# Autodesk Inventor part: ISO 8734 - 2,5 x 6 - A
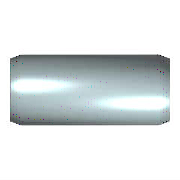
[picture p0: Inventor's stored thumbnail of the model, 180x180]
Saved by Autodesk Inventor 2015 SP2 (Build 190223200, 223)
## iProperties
IsCustomPart: 0
Created: 2012-02
Part Number: ISO 8734 - 2,5 x 6 - A
Material: Stahl
Description: Zylinderstift
Document SubType Name: Modeling
Standard: ISO 8734
Designer: rYan
Standards Organization: DIN
Language: de-DE
Size Designation: 2,5 x 6 - A
Categories: <MemberInstance><Categories><Category DisplayName="Verbindungselemente" InternalName="e4da775c-781d-43d5-af7c-5136215cf5a6" Mnemonic="FSTN"><Category DisplayNam
Density: 7.85 g/cm^3
Appearance: Platte
Author: rYan
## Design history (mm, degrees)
sketch "Skizze"
  geometry: C1 r 1.25 at (0, 0); 1 further point
  constraints: 1 centre point, 1 coincident
  dimensions: "d1" = 2.5 diameter of C1 (= NND)
extrude "Körper" new body sketch "Skizze" distance "d2" = 6 (= NLG); taper "d3" = 0 deg
body "Solid1"
chamfer "Fase1" distance "d4" = 0.4 (= PHH); stored, may be unused: angle "d5" = 15 deg (= FAWI), second distance "d11" = 0.4 (= PHH)
chamfer "Fase2" distance "d8" = 0.4 (= PHH); stored, may be unused: angle "d9" = 15 deg (= FAWI), second distance "d12" = 0.4 (= PHH)
other parameters: "NND" = 2.5 [user parameter; used in 1 equation term], "NLG" = 6 [user parameter; used in 1 equation term], "PHH" = 0.4 [user parameter; used in 5 equation terms], "FAWI" = 15 deg [user parameter; used in 2 equation terms], "d13" = 0, "d15" = 0, "d16" = 0, "PHH2" = 0.4 (= PHH) [user parameter], "FAWI2" = 15 deg [user parameter]
